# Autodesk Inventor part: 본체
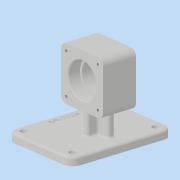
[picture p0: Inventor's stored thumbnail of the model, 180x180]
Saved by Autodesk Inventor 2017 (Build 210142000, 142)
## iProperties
Part Number: 본체
Material: 일반
Document SubType Name: Modeling
Designer: 222
Density: 1 g/cm^3
Appearance: 기본값
Author: 222
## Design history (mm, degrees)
sketch "스케치1"
  geometry: L1 (-32, 32)-(32, 32); L2 (32, 32)-(32, -32); L3 (32, -32)-(-32, -32); L4 (-32, -32)-(-32, 32); L5 (-32, 32)-(32, -32); L6 (32, 32)-(-32, -32); 1 further point
  constraints: 12 end point, 2 midpoint, 2 parallel, 1 horizontal, 1 perpendicular
  dimensions: "d0" = 64 distance of L2.end L3.end; "d1" = 64 distance of L1.end L2.end
extrude "돌출1" new body sketch "스케치1" stored distance "d2" = 42; taper "d3" = 0 deg
sketch "스케치2"
  geometry: C1 r 21 at (0, 0); 1 further point
  constraints: 1 centre point, 1 coincident
  dimensions: "d4" = 42 diameter of C1
extrude "돌출2" cut sketch "스케치2" distance "d5" = 15; taper "d6" = 0 deg
sketch "스케치3"
  geometry: C1 r 18 at (0, 0); 1 further point
  constraints: 1 centre point, 1 coincident
  dimensions: "d7" = 36 diameter of C1
extrude "돌출3" cut sketch "스케치3" distance "d8" = 15; taper "d9" = 0 deg
fillet "모깎기1" dims "d10" = 8
hole "구멍1" diameter "d13" = 3.242; stored, may be unused: countersink angle "d17" = 90 deg, drill point angle "d19" = 118 deg; dims "d11" = 10, "d12" = 10, "d14" = 8, "d15" = 4, "d16" = 2, "d18" = 10
node "작업 평면1"
sketch "스케치4"
  geometry: L1 (36, 65)-(-62, 65); L2 (-62, 65)-(-62, -65); L3 (-62, -65)-(36, -65); L4 (36, -65)-(36, 65); 1 further point
  constraints: 8 end point, 2 parallel, 1 horizontal, 1 perpendicular
  dimensions: "d21" = 130 distance of L3.end L1.start; "d22" = 98 distance of L2.end L3.end; "d23" = 65 distance from line of point (0, 0) L3; "d25" = 62 distance from line of L2 point (0, 0)
extrude "돌출4" join sketch "스케치4" distance "d26" = 10; taper "d27" = 0 deg
sketch "스케치5"
  geometry: L1 (24, -32)-(-24, -32) reference; L2 (36, -60)-(-62, -60) reference; L3 (-20, -32)-(-20, -60); L4 (20, -32)-(20, -60); L5 (-20, -32)-(20, -32); L6 (-20, -60)-(20, -60); 1 further point
  constraints: 8 end point, 4 point on line, 2 collinear, 2 vertical
  dimensions: "d28" = 40 distance between parallel lines of L4 L3; "d29" = 20 distance from line of point (0, 0) L3
extrude "돌출5" join sketch "스케치5" stored distance "d30" = 8; taper "d31" = 0 deg
sketch "스케치6"
  geometry: L1 (-32, -21)-(-32, 21) reference; L2 (-32, 4)-(-60, 4) reference; L3 (-60, -4)-(-32, -4) reference; L4 (-60, -65)-(-60, 65) reference; L5 (-32, 17)-(-60, 17); L6 (-32, -17)-(-60, -17); L7 (-32, 17)-(-32, 4); L8 (-32, 4)-(-60, 4); L9 (-60, 4)-(-60, 17); L10 (-32, -4)-(-32, -17); L11 (-32, -4)-(-60, -4); L12 (-60, -4)-(-60, -17); 1 further point
  constraints: 16 end point, 4 point on line, 3 collinear, 3 perpendicular, 2 horizontal
  dimensions: "d32" = 34 distance between parallel lines of L6 L5; "d33" = 17 distance from line of point (0, 0) L5
extrude "돌출6" join sketch "스케치6" stored distance "d34" = 8; taper "d35" = 0 deg
fillet "모깎기2" dims "d36" = 12
hole "구멍2" diameter "d39" = 9; stored, may be unused: countersink angle "d43" = 90 deg, drill point angle "d45" = 118 deg; dims "d37" = 10, "d38" = 10, "d40" = 8, "d41" = 4, "d42" = 2, "d44" = 10
node "작업 평면2"
fillet "모깎기3" dims "d46" = 3
fillet "모깎기4" dims "d47" = 3
fillet "모깎기5" dims "d48" = 0.3
chamfer "모따기1" distance "d49" = 1; stored, may be unused: second distance "d50" = 2, angle "d51" = 45 deg
sketch "스케치7"
  geometry: L1 (-62, 53)-(-62, -53) reference; 2 further points
  constraints: 1 horizontal alignment, 1 other
  dimensions: "d52" = 10 distance from line of point (-52, 0) L1
feature "엠보싱1" sketch "스케치7" dims "d0" = 64, "d1" = 64, "d53" = 0.5, "d54" = 0
node "솔리드1"
mirror "미러1"
mirror "미러2"
mirror "미러3"
mirror "미러4"
mirror "미러5"
